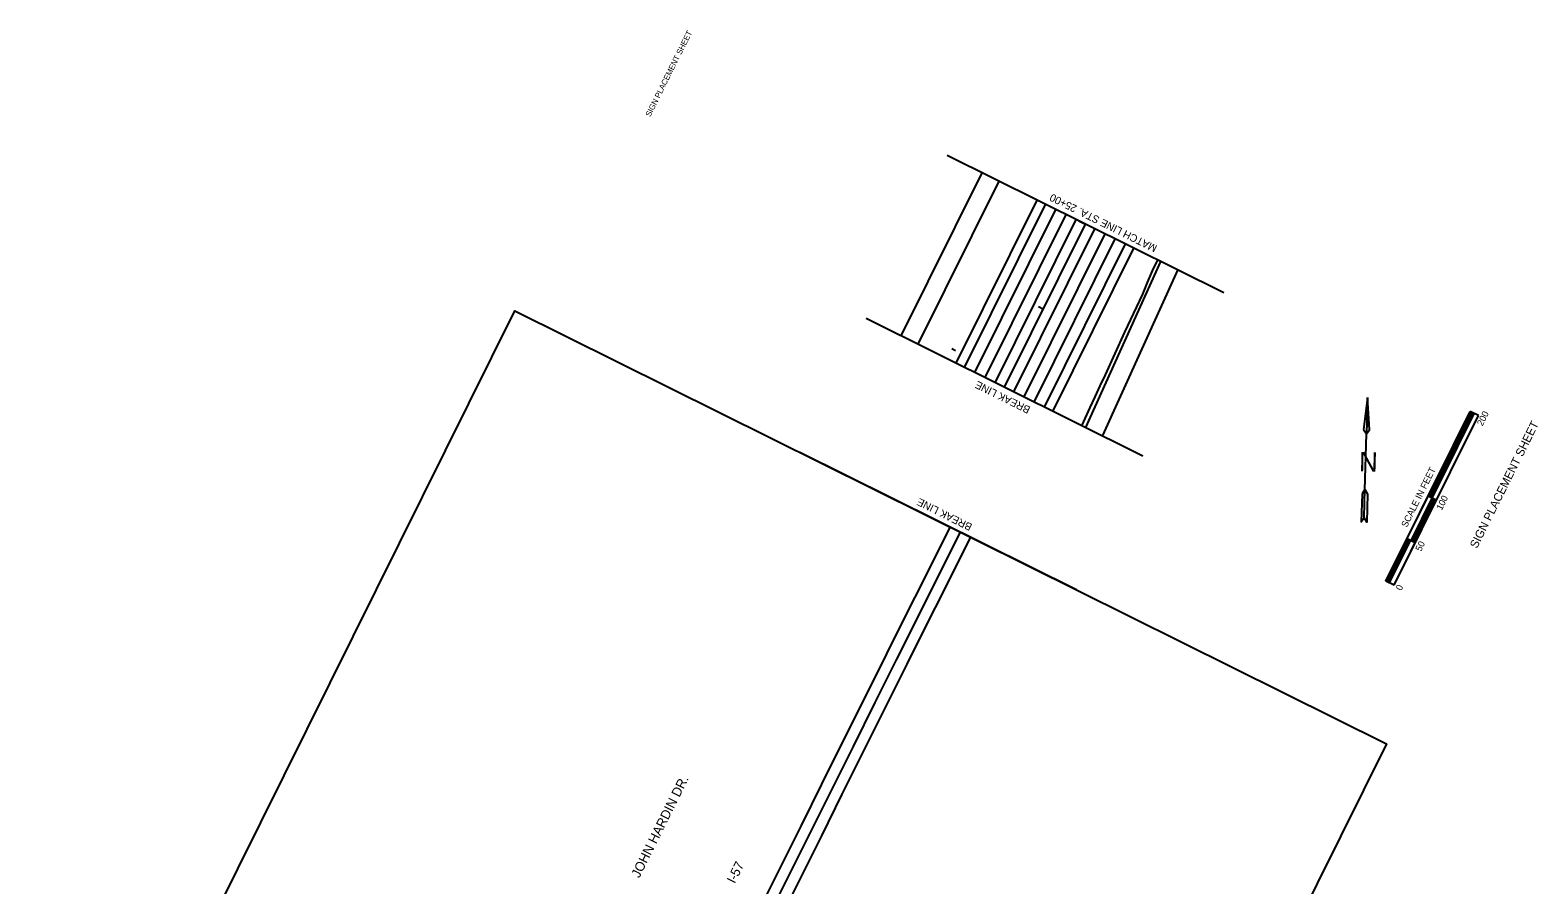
# Model space of a CAD drawing. Extents: x 1288247 to 1295361, y 218673 to 226414.
# Drawn here: x 1288247 to 1289838, y 219555 to 220457 of the extents above; entities that cross this region are included whole.
import ezdxf

# ---------------------------------------------------------------- set-up
doc = ezdxf.new("R2010")
doc.units = 0
for name, color, linetype in [('5', 7, 'Continuous'), ('60', 7, 'Continuous'), ('G-ANNO-TEXT', 7, 'Continuous'), ('Level 10', 7, 'Continuous'), ('Plan Notes', 7, 'Continuous'), ('R_Border', 7, 'Continuous'), ('R_Horz Alg', 7, 'Continuous'), ('R_Horz Alg Stationing', 7, 'Continuous'), ('R_No Plot', 7, 'Continuous'), ('R_Striping_Existing', 7, 'Continuous'), ('S_EDGE_PAVEMENT', 7, 'Continuous'), ('S_SHOULDER', 7, 'Continuous'), ('S_SIGN', 7, 'Continuous')]:
    doc.layers.add(name, color=color, linetype=linetype)

msp = doc.modelspace()

# ---------------------------------------------------------------- linework, layer by layer
at = {"layer": '5'}
for p, q in [((1289507.2, 220179.3), (1289215.1, 220324.3)), ((1289421.7, 220007.1), (1289129.6, 220152.1)), ((1289351.5, 219865.8), (1289059.4, 220010.9))]:
    msp.add_line(p, q, dxfattribs=at)
at = {"layer": 'G-ANNO-TEXT'}
for p, q in [((1289658.6, 220069), (1289654.5, 220035)), ((1289654.5, 220035), (1289657.5, 220030.5)), ((1289656, 219971.6), (1289657.5, 220030.5))]:
    msp.add_line(p, q, dxfattribs=at)
for points in [[(1289658.6, 220068.8), (1289657.5, 220030.5), (1289660.8, 220034.9)], [(1289652.9, 219967.1), (1289652.1, 219937.6), (1289655.2, 219942.4), (1289655.9, 219971.7)], [(1289655.9, 219971.7), (1289658.7, 219966.9), (1289657.9, 219937.4), (1289655.2, 219942.4)]]:
    msp.add_lwpolyline(points, close=True, dxfattribs=at)
at = {"layer": 'Level 10'}
for p, q in [((1289686.8, 219870.8), (1289775.7, 220049.9)), ((1289713.8, 219946.7), (1289767.1, 220054.2)), ((1289723.4, 219964.3), (1289767.8, 220053.8)), ((1289724.1, 219963.9), (1289768.5, 220053.5)), ((1289724.8, 219963.6), (1289769.3, 220053.1)), ((1289725.5, 219963.2), (1289770, 220052.8)), ((1289726.2, 219962.8), (1289770.7, 220052.4)), ((1289727, 219962.5), (1289771.4, 220052.1)), ((1289775.7, 220049.9), (1289767.1, 220054.2)), ((1289678.2, 219875), (1289749.3, 220018.4)), ((1289727, 219962.5), (1289753.6, 220016.2)), ((1289704.7, 219917.7), (1289727, 219962.5)), ((1289705.4, 219917.3), (1289727.7, 219962.1)), ((1289706.2, 219917), (1289728.4, 219961.8)), ((1289706.9, 219916.6), (1289729.1, 219961.4)), ((1289707.6, 219916.3), (1289729.8, 219961.1)), ((1289708.3, 219915.9), (1289730.5, 219960.7)), ((1289731.3, 219960.4), (1289722.7, 219964.6)), ((1289704.6, 219906.6), (1289722.4, 219942.4)), ((1289678.9, 219874.7), (1289701.1, 219919.5)), ((1289679.6, 219874.3), (1289701.9, 219919.1)), ((1289680.3, 219874), (1289702.6, 219918.8)), ((1289681.1, 219873.6), (1289703.3, 219918.4)), ((1289681.8, 219873.3), (1289704, 219918.1)), ((1289709, 219915.6), (1289700.4, 219919.8)), ((1289678.2, 219875), (1289696, 219910.9)), ((1289686.8, 219870.8), (1289678.2, 219875))]:
    msp.add_line(p, q, dxfattribs=at)
at = {"layer": 'R_Horz Alg'}
msp.add_line((1289275.6, 220079.6), (1289361.1, 220251.8), dxfattribs=at)
at = {"layer": 'R_Horz Alg Stationing'}
for points in [[(1289354, 220255.4), (1289361.1, 220251.8)], [(1289311.3, 220164.9), (1289316.7, 220162.2)]]:
    msp.add_lwpolyline(points, dxfattribs=at)
at = {"layer": 'R_No Plot'}
msp.add_lwpolyline([(1288247.2, 219130.2), (1288758.7, 220160.2), (1289678.8, 219703.3), (1289167.3, 218673.3)], close=True, dxfattribs=at)
at = {"layer": 'R_Striping_Existing'}
for p, q in [((1289244.3, 220095.2), (1289329.8, 220267.4)), ((1289255, 220089.8), (1289340.5, 220262)), ((1289296.2, 220069.4), (1289381.7, 220241.6)), ((1289307, 220064), (1289392.5, 220236.2))]:
    msp.add_line(p, q, dxfattribs=at)
for points in [[(1288704.4, 218903.1), (1288721.1, 218937.1), (1288742.4, 218979.7), (1288765.5, 219025.6), (1288788.6, 219071.6), (1288813.1, 219120.9), (1288836.4, 219167.7), (1288858.7, 219212.5), (1288881.1, 219257.4), (1288903.1, 219301.3), (1288925.8, 219346.5), (1288949.2, 219393.1), (1288971.2, 219437.3), (1288992.2, 219479.2), (1289015.1, 219525.1), (1289038.3, 219571.5), (1289061.2, 219617.1), (1289082.9, 219660.9), (1289105.4, 219706.1), (1289128.5, 219752.4), (1289151.4, 219798.2), (1289169.8, 219835.2), (1289192.8, 219881), (1289218.3, 219932)], [(1288715.1, 218897.8), (1288731.9, 218931.7), (1288753.2, 218974.3), (1288776.3, 219020.2), (1288799.3, 219066.3), (1288823.9, 219115.6), (1288847.1, 219162.3), (1288869.5, 219207.2), (1288891.9, 219252), (1288913.8, 219295.9), (1288936.6, 219341.1), (1288959.9, 219387.7), (1288982, 219431.9), (1289002.9, 219473.8), (1289025.9, 219519.7), (1289049.1, 219566.1), (1289071.9, 219611.8), (1289093.6, 219655.5), (1289116.2, 219700.7), (1289139.2, 219747), (1289162.1, 219792.9), (1289180.6, 219829.8), (1289203.5, 219875.6), (1289229, 219926.7)]]:
    msp.add_lwpolyline(points, dxfattribs=at)
at = {"layer": 'S_EDGE_PAVEMENT'}
for p, q in [((1289166.4, 220133.9), (1289251.9, 220306.1)), ((1289184.3, 220125), (1289269.8, 220297.2)), ((1289233.5, 220100.5), (1289319, 220272.7)), ((1289265.8, 220084.5), (1289351.3, 220256.7)), ((1289285.5, 220074.7), (1289371, 220246.9)), ((1289317.7, 220058.7), (1289403.2, 220230.9)), ((1289361.3, 220037.1), (1289440.6, 220212.3)), ((1289379.5, 220028.8), (1289458.9, 220204.1))]:
    msp.add_line(p, q, dxfattribs=at)
msp.add_lwpolyline([(1288725.9, 218892.5), (1288742.6, 218926.4), (1288763.9, 218968.9), (1288787, 219014.9), (1288810, 219060.9), (1288834.6, 219110.2), (1288857.8, 219157), (1288880.2, 219201.8), (1288902.6, 219246.6), (1288924.5, 219290.6), (1288947.3, 219335.7), (1288970.6, 219382.4), (1288992.7, 219426.6), (1289013.6, 219468.5), (1289036.6, 219514.3), (1289059.8, 219560.7), (1289082.7, 219606.4), (1289104.4, 219650.2), (1289126.9, 219695.4), (1289150, 219741.7), (1289172.9, 219787.5), (1289191.3, 219824.4), (1289214.2, 219870.2), (1289239.7, 219921.3)], dxfattribs=at)
at = {"layer": 'S_SHOULDER'}
for p, q in [((1289224.6, 220105), (1289310.1, 220277.1)), ((1289326.7, 220054.2), (1289412.2, 220226.4))]:
    msp.add_line(p, q, dxfattribs=at)
msp.add_lwpolyline([(1289357.2, 220039.1), (1289360.7, 220046.7), (1289366, 220058.2), (1289371.3, 220069.7), (1289376.6, 220081.2), (1289382, 220092.7), (1289392.3, 220115.2), (1289402.5, 220137.8), (1289412, 220157.9), (1289421.4, 220177.9), (1289426.6, 220190.1), (1289431.9, 220202.4), (1289437.3, 220214)], dxfattribs=at)
at = {"layer": 'S_SIGN'}
msp.add_lwpolyline([(1289220, 220120.5), (1289223.8, 220118.6)], dxfattribs=at)

# ---------------------------------------------------------------- texts
at = {"layer": '60'}
msp.add_text('SIGN PLACEMENT SHEET', height=8.87, rotation=63.5913, dxfattribs=at).set_placement((1289774.2, 219908.9))
at = {"layer": 'G-ANNO-TEXT'}
msp.add_text('N', height=20.4, rotation=358.4728, dxfattribs=at).set_placement((1289649.6, 219991.1))
at = {"layer": 'Level 10'}
for s, height, p in [('200', 7, (1289780.1, 220038.3)), ('SCALE IN FEET', 7.001, (1289700.2, 219931.1)), ('100', 7, (1289737.1, 219949.3)), ('50', 7, (1289715.1, 219905.8)), ('0', 7, (1289694.4, 219864.5))]:
    msp.add_text(s, height=height, rotation=63.6051, dxfattribs=at).set_placement(p)
at = {"layer": 'Plan Notes'}
for s, height, rotation, p in [('MATCH LINE STA. 25+00', 8, 153.5913, (1289437.4, 220228.9)), ('BREAK LINE', 8, 153.5913, (1289303.6, 220058.6)), ('BREAK LINE', 8, 153.5913, (1289242.2, 219935)), ('JOHN HARDIN DR.', 10, 63.5913, (1288890.1, 219561.2)), ('I-57', 10, 63.5913, (1288990.9, 219555.3))]:
    msp.add_text(s, height=height, rotation=rotation, dxfattribs=at).set_placement(p)
at = {"layer": 'R_Border'}
msp.add_text('SIGN PLACEMENT SHEET', height=6, rotation=63.5931, dxfattribs=at).set_placement((1288901.7, 220364.6))

doc.saveas('drawing.dxf')
